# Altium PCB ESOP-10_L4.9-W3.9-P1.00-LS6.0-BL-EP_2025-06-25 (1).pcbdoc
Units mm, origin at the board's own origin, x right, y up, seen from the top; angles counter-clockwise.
Board outline 35.05 x 32.97 mm, 2 copper layers (Top Layer, Bottom Layer); 1 components, 0 nets, 11 pads, 0 vias.
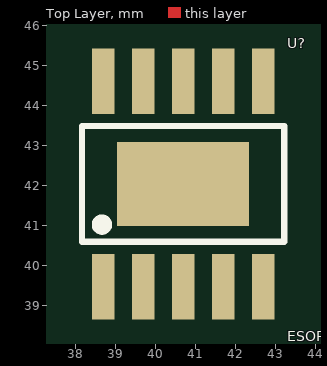
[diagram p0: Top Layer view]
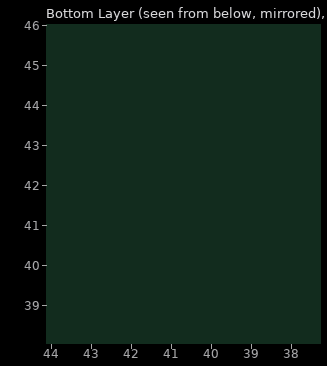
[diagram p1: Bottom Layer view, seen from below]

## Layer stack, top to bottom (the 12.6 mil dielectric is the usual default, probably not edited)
Top Layer: signal copper (thickness not stored)
Dielectric: dielectric 0.32, FR-4, Dk 4.8
Bottom Layer: signal copper (thickness not stored)

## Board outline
60.45,25.4 25.4,25.4 25.4,58.374 60.45,58.374

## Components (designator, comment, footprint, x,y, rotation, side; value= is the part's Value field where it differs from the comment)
U? "ESOP-10_L4.9-W3.9-P1.00-LS6.0-BL-EP" ESOP-10_L4.9-W3.9-P1.00-LS6.0-BL-EP 40.702,41.76 r0 top

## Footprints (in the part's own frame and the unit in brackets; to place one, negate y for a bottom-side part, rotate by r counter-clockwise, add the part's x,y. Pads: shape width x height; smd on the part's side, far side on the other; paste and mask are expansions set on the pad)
ESOP-10_L4.9-W3.9-P1.00-LS6.0-BL-EP [mm]
  rect 0.56x1.64 smd paste+0 mask+0.051: 1(-2,-2.3) 2(-1,-2.3) 3(0,-2.3) 4(1,-2.3) 5(2,-2.3) 6(2,2.84) 7(1,2.84) 8(0,2.84) 9(-1,2.84) 10(-2,2.84)
  rect 3.3x2.1 smd paste+0 mask+0.051: 11(0,0.27)
  silkscreen extent -2.53,-1.18 2.53,1.72

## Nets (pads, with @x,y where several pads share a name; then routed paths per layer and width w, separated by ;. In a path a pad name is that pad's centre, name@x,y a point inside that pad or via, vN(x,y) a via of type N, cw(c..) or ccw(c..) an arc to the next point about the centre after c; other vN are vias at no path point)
pads on no net: U?.1 U?.2 U?.3 U?.4 U?.5 U?.6 U?.7 U?.8 U?.9 U?.10 U?.11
